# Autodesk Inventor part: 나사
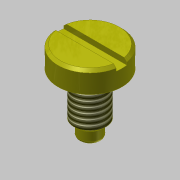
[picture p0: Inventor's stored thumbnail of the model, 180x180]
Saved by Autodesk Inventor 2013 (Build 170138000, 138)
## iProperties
Created: 2019-10
Part Number: 나사
Material: 스테인리스강
Document SubType Name: Modeling
Designer: mduedu
Density: 1 g/cm^3
Author: mduedu
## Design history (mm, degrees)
sketch "스케치1"
  geometry: L1 (0, 0)-(-6, 0); L2 (-6, 0)-(-6, -4); L3 (-6, -4)-(0, -4); L4 (0, -4)-(0, 0); L5 (0, -4)-(-3, -4); L6 (-3, -4)-(-3, -12.5); L7 (-3, -12.5)-(0, -12.5); L8 (0, -12.5)-(0, -4); L9 (0, -12.5)-(-2, -12.5); L10 (-2, -12.5)-(-2, -15); L11 (-2, -15)-(0, -15); L12 (0, -15)-(0, -12.5)
  constraints: 24 end point, 6 parallel, 3 horizontal, 3 perpendicular
  dimensions: "d0" = 15 distance between parallel lines of L11 L1; "d2" = 4 distance of L1.end L2.end; "d3" = 2.5 distance of L9.end L10.end; "d4" = 12 diameter of L2 L4; "d5" = 6 diameter of L6 L8; "d6" = 4 diameter of L10 L12
revolve "회전1" sketch "스케치1" stored, may be unused: angle "d7" = 90 deg
sketch "스케치2"
  geometry: L1 (2, -15)-(-2, -15) reference; L2 (-2, -15)-(-2, -12.5) reference; L3 (-2, -12.5)-(-3, -12.5) reference; L4 (-3, -12.5)-(-3, -4) reference; L5 (-3, -4)-(-6, -4) reference; L6 (-6, -4)-(-6, 0) reference; L7 (-6, 0)-(6, 0) reference; L8 (6, 0)-(6, -4) reference; L9 (6, -4)-(3, -4) reference; L10 (3, -4)-(3, -12.5) reference; L11 (3, -12.5)-(2, -12.5) reference; L12 (2, -12.5)-(2, -15) reference; L13 (0, 0)-(0, -15); L14 (-3, -4)-(-2.25, -4); L15 (-2.25, -4)-(-2.25, -4.5); L16 (-2.25, -4.5)-(-3, -4.5); L17 (-3, -4.5)-(-3, -4)
  constraints: 10 end point, 2 parallel, 1 horizontal, 1 midpoint, 1 perpendicular
  dimensions: "d8" = 4.5 diameter of L15 L13; "d10" = 0.5 distance between parallel lines of L16 L14
revolve "회전2" sketch "스케치2" stored, may be unused: angle "d11" = 90 deg
chamfer "모따기1" distance "d12" = 0.5; stored, may be unused: second distance "d13" = 2, angle "d14" = 45 deg
feature "스레드1" dims "d19" = 10, "d20" = 0
chamfer "모따기2" distance "d15" = 0.5; stored, may be unused: second distance "d16" = 2, angle "d17" = 45 deg
fillet "모깎기1" dims "d18" = 0.5
sketch "스케치3"
  geometry: L1 (-7.5, -1)-(7.5, -1); L2 (7.5, -1)-(7.5, 1); L3 (7.5, 1)-(-7.5, 1); L4 (-7.5, 1)-(-7.5, -1); L5 (-7.5, -1)-(7.5, 1); L6 (7.5, -1)-(-7.5, 1); 1 further point
  constraints: 12 end point, 2 midpoint, 2 parallel, 1 horizontal, 1 perpendicular
  dimensions: "d21" = 2 distance of L1.end L2.end; "d23" = 15 distance of L2.end L3.end
extrude "돌출1" cut sketch "스케치3" distance "d24" = 1; taper "d25" = 0 deg
node "솔리드1"
node "절단 모서리 투영1"
